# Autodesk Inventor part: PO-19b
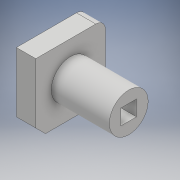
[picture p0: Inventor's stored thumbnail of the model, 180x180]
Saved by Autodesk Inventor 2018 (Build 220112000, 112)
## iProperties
Created: 2020-01
Part Number: PO-19b
Material: Générique
Document SubType Name: Modeling
Designer: TJ
Density: 1 g/cm^3
Appearance: Par défaut
Author: TJ
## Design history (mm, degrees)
sketch "Esquisse1"
  geometry: L1 (18, 18)-(-18, 18); L2 (-18, 18)-(-18, -18); L3 (-18, -18)-(18, -18); L4 (18, -18)-(18, 18); 1 further point
  constraints: 8 end point, 2 parallel, 1 horizontal, 1 perpendicular
  dimensions: "d0" = 36 distance of L3.end L1.start; "d1" = 36 distance of L1.start L1.end (= d0); "d2" = 18 distance from line of L4 point (0, 0) (= 0.5 x d0); "d3" = 18 distance from line of L1 point (0, 0) (= 0.5 x d0)
extrude "Extrusion1" new body sketch "Esquisse1" distance "d4" = 10; taper "d5" = 0 deg
sketch "Esquisse3"
  geometry: L1 (-10, 10)-(10, 10); L2 (10, 10)-(10, -10); L3 (10, -10)-(-10, -10); L4 (-10, -10)-(-10, 10); L5 (-10, 10)-(10, -10); L6 (10, 10)-(-10, -10); 1 further point
  constraints: 12 end point, 2 midpoint, 2 parallel, 1 horizontal, 1 perpendicular
  dimensions: "d10" = 20 distance of L1.start L1.end; "d11" = 20 distance of L3.end L1.start (= d10)
extrude "Extrusion3" join sketch "Esquisse3" distance "d12" = 30; taper "d13" = 0 deg
sketch "Esquisse5"
  geometry: L1 (-4, -4)-(4, -4); L2 (4, -4)-(4, 4); L3 (4, 4)-(-4, 4); L4 (-4, 4)-(-4, -4); L5 (-4, -4)-(4, 4); L6 (4, -4)-(-4, 4); 1 further point
  constraints: 12 end point, 2 midpoint, 2 parallel, 1 horizontal, 1 perpendicular
  dimensions: "d17" = 8 distance of L3.end L1.start; "d18" = 8 distance of L2.end L3.end
extrude "Extrusion5" cut sketch "Esquisse5" extent not by distance; stored distance "d19" = 10; taper "d20" = 0 deg
fillet "Congé2" dims "d21" = 5
fillet "Congé3" dims "d25" = 10
chamfer "Chanfrein2" distance "d26" = 5; stored, may be unused: second distance "d27" = 2, angle "d28" = 45 deg
node "Solide1"
